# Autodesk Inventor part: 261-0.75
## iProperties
Created: 2009-09
Part Number: 261-0.75
Document SubType Name: Modeling
Designer: D Cole
Density: 1 g/cm^3
Translation Standard: IGES 5.3
File Name: No Iges File Name specified
Preprocessor: AutoDesk Inventor R12.0
Postprocessor: Build: 320, Release: 2008 SP2 - Date: Mon 11/26/2007
Sent Units: MM
Uncertainty: 0.01
Author: D Cole
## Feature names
1. Base1
